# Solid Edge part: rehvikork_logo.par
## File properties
Author: KULL
Template: Iso Metric Part.par
Last saved by: KULL
Revision: 4
Application: Solid Edge
Accuracy: 0,990
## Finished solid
Body 1: solid body, 86 faces, 199 edges, 116 vertices, 2 separate solids.
  Faces by surface: spline 40, blend 36, sphere 8, cone 1, torus 1
  Edges by curve: intersection 112, line 32, circle 29, curve on surface 26
Bounding box of the edges (mm; curved faces can reach further): 1.405 x 13.917 x 13.917, from (-0.4589, -6.9587, -6.9587) to (0.946, 6.9587, 6.9587).
Conical faces (half-angle, radius in mm at the cone's reference point): 11.8765 deg R7 x1
Toroidal faces (ring radius, tube radius in mm): R6.763 r0.2 x1
Spherical faces by radius (mm): R0.2 x4, R33.3132 x2, R34.0132 x2
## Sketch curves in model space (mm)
circle centre (4.1723, 0, 0) radius 7
arc centre (4.1723, -5.154, -2.9757) radius 0.4 from (4.1723, -5.5537, -2.9929) through (4.1723, -5.5004, -3.1757) to (4.1723, -5.3688, -3.3131)
arc centre (4.1723, 0, 5.1235) radius 10 from (4.1723, 5.3688, -3.3131) through (4.1723, 0, -4.8765) to (4.1723, -5.3688, -3.3131)
arc centre (4.1723, 5.154, -2.9757) radius 0.4 from (4.1723, 5.3688, -3.3131) through (4.1723, 5.5004, -3.1757) to (4.1723, 5.5537, -2.9929)
arc centre (4.1723, -4.437, -2.5617) radius 10 from (4.1723, 0.1849, 6.3061) through (4.1723, 4.2232, 2.4383) to (4.1723, 5.5537, -2.9929)
arc centre (4.1723, 0, 5.9514) radius 0.4 from (4.1723, 0.1849, 6.3061) through (4.1723, 0, 6.3514) to (4.1723, -0.1849, 6.3061)
arc centre (4.1723, 4.437, -2.5617) radius 10 from (4.1723, -0.1849, 6.3061) through (4.1723, -4.2232, 2.4383) to (4.1723, -5.5537, -2.9929)
arc centre (4.1723, -0.6763, 0.7482) radius 0.2 from (4.1723, -0.6763, 0.5482) through (4.1723, -0.8218, 0.6109) to (4.1723, -0.8763, 0.7482)
line (4.1723, -0.8763, 0.7482) -> (4.1723, -0.8763, 2.26)
arc centre (4.1723, -1.0763, 2.26) radius 0.2 from (4.1723, -0.8763, 2.26) through (4.1723, -0.939, 2.4055) to (4.1723, -1.0763, 2.46)
line (4.1723, -1.0763, 2.46) -> (4.1723, -1.901, 2.46)
arc centre (4.1723, -1.901, 2.26) radius 0.2 from (4.1723, -1.901, 2.46) through (4.1723, -2.0465, 2.3973) to (4.1723, -2.101, 2.26)
line (4.1723, -2.101, 2.26) -> (4.1723, -2.101, 0)
line (4.1723, -2.101, -2.26) -> (4.1723, -2.101, 0)
arc centre (4.1723, -1.901, -2.26) radius 0.2 from (4.1723, -1.901, -2.46) through (4.1723, -2.0465, -2.3973) to (4.1723, -2.101, -2.26)
line (4.1723, -1.0763, -2.46) -> (4.1723, -1.901, -2.46)
arc centre (4.1723, -1.0763, -2.26) radius 0.2 from (4.1723, -0.8763, -2.26) through (4.1723, -0.939, -2.4055) to (4.1723, -1.0763, -2.46)
line (4.1723, -0.8763, -0.7482) -> (4.1723, -0.8763, -2.26)
arc centre (4.1723, -0.6763, -0.7482) radius 0.2 from (4.1723, -0.6763, -0.5482) through (4.1723, -0.8218, -0.6109) to (4.1723, -0.8763, -0.7482)
line (4.1723, 0, -0.5482) -> (4.1723, -0.6763, -0.5482)
line (4.1723, 0, -0.5482) -> (4.1723, 0.6763, -0.5482)
arc centre (4.1723, 0.6763, -0.7482) radius 0.2 from (4.1723, 0.6763, -0.5482) through (4.1723, 0.8218, -0.6109) to (4.1723, 0.8763, -0.7482)
line (4.1723, 0.8763, -0.7482) -> (4.1723, 0.8763, -2.26)
arc centre (4.1723, 1.0763, -2.26) radius 0.2 from (4.1723, 0.8763, -2.26) through (4.1723, 0.939, -2.4055) to (4.1723, 1.0763, -2.46)
line (4.1723, 1.0763, -2.46) -> (4.1723, 1.901, -2.46)
arc centre (4.1723, 1.901, -2.26) radius 0.2 from (4.1723, 1.901, -2.46) through (4.1723, 2.0465, -2.3973) to (4.1723, 2.101, -2.26)
line (4.1723, 2.101, -2.26) -> (4.1723, 2.101, 0)
line (4.1723, 2.101, 2.26) -> (4.1723, 2.101, 0)
arc centre (4.1723, 1.901, 2.26) radius 0.2 from (4.1723, 1.901, 2.46) through (4.1723, 2.0465, 2.3973) to (4.1723, 2.101, 2.26)
line (4.1723, 1.0763, 2.46) -> (4.1723, 1.901, 2.46)
arc centre (4.1723, 1.0763, 2.26) radius 0.2 from (4.1723, 0.8763, 2.26) through (4.1723, 0.939, 2.4055) to (4.1723, 1.0763, 2.46)
line (4.1723, 0.8763, 0.7482) -> (4.1723, 0.8763, 2.26)
arc centre (4.1723, 0.6763, 0.7482) radius 0.2 from (4.1723, 0.6763, 0.5482) through (4.1723, 0.8218, 0.6109) to (4.1723, 0.8763, 0.7482)
line (4.1723, 0, 0.5482) -> (4.1723, 0.6763, 0.5482)
line (4.1723, 0, 0.5482) -> (4.1723, -0.6763, 0.5482)
arc centre (4.1723, 4.1615, -2.4026) radius 0.4 from (4.1723, 4.355, -2.7527) through (4.1723, 4.5079, -2.6026) to (4.1723, 4.5614, -2.3952)
arc centre (4.1723, 0, 5.1235) radius 9 from (4.1723, 4.355, -2.7527) through (4.1723, 0, -3.8765) to (4.1723, -4.355, -2.7527)
arc centre (4.1723, -4.1615, -2.4026) radius 0.4 from (4.1723, -4.5614, -2.3952) through (4.1723, -4.5079, -2.6026) to (4.1723, -4.355, -2.7527)
arc centre (4.1723, 4.437, -2.5617) radius 9 from (4.1723, -4.5614, -2.3952) through (4.1723, -3.3572, 1.9383) to (4.1723, -0.2064, 5.1479)
arc centre (4.1723, 0, 4.8053) radius 0.4 from (4.1723, 0.2064, 5.1479) through (4.1723, 0, 5.2053) to (4.1723, -0.2064, 5.1479)
arc centre (4.1723, -4.437, -2.5617) radius 9 from (4.1723, 0.2064, 5.1479) through (4.1723, 3.3572, 1.9383) to (4.1723, 4.5614, -2.3952)
circle centre (0, 0, 0) radius 8
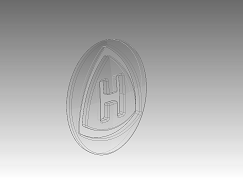
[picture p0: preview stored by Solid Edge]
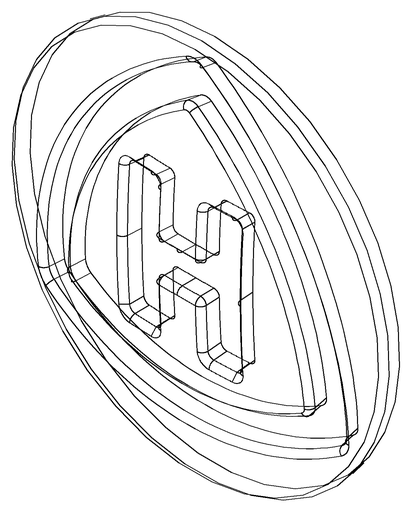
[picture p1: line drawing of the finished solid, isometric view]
